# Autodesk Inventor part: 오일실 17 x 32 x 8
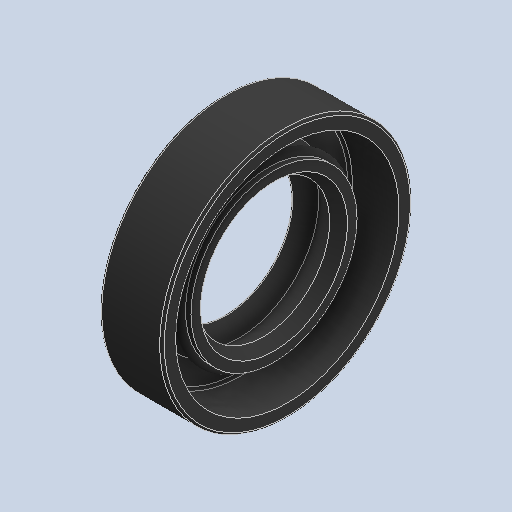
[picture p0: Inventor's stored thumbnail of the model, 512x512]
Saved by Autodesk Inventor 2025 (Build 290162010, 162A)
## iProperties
Created: 2024-07
Part Number: 오일실 17 x 32 x 8
Material: 고무
Description: 오일-실
Document SubType Name: Modeling
Designer: Admin
Density: 0.93 g/cm^3
Appearance: 기본값
Author: jhkim
Sending System: Autodesk Inventor 2025
Preprocessor: ST-DEVELOPER v20
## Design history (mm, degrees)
feature "Solid1"
node "솔리드1"
